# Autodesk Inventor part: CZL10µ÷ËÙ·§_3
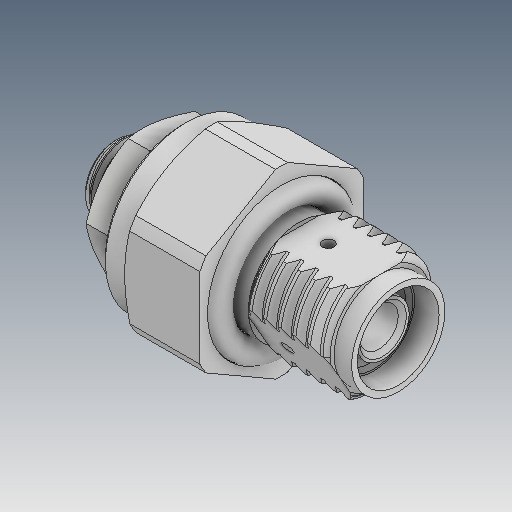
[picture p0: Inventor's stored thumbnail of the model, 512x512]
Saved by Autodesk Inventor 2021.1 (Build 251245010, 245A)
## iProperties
Created: 2019-04
Part Number: CZL10µ÷ËÙ·§_3
Material: Ogólny
Document SubType Name: Modeling
Designer: user
Density: 1 g/cm^3
Appearance: Domyślna
Author: user
Revision Number: ÈÎºÎ
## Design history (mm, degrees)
feature "ÊäÈë1"
feature "ÊäÈë2"
feature "ÊäÈë3"
node "Bryła1"
node "Bryła2"
node "Bryła3"
